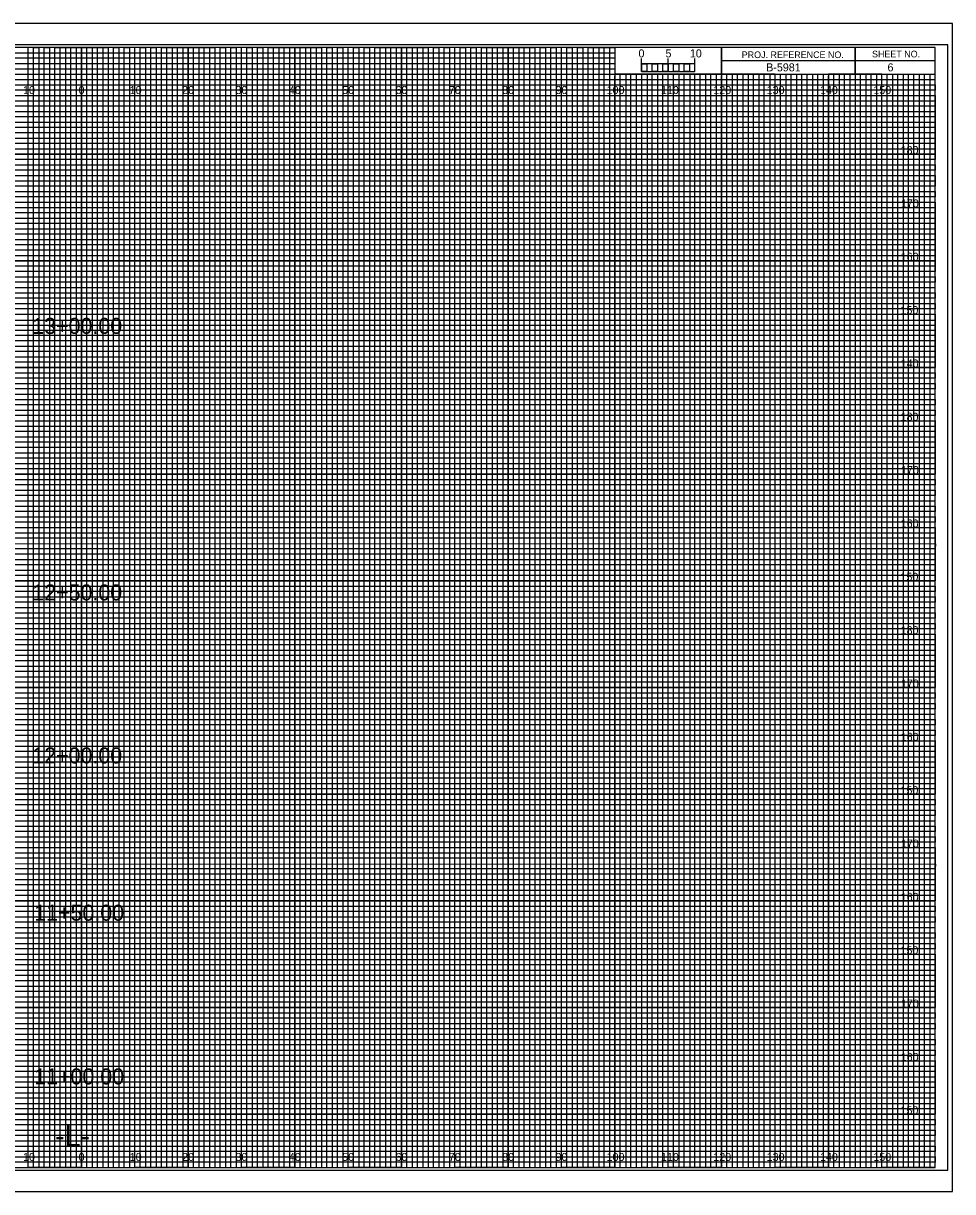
# Model space of a CAD drawing. Extents: x -13 to 323, y -5 to 4174.
# Drawn here: x 149.1 to 323.3, y -4.5 to 214.5 of the extents above; entities that cross this region are included whole.
import ezdxf

# ---------------------------------------------------------------- set-up
doc = ezdxf.new("R2010")
doc.units = 0
for name, color, linetype in [('Exist Cross Section Cell', 7, 'Continuous'), ('Exist XS Center Line Elevation Label', 7, 'Continuous'), ('Exist XS Ground Line', 7, 'Continuous'), ('Prop CMT Concrete Structures', 7, 'Continuous'), ('Prop CMT Guardrail Graphics', 7, 'Continuous'), ('Prop CMT Pvmt Course 1', 7, 'Continuous'), ('Prop CMT Pvmt Course 2', 7, 'Continuous'), ('Prop CMT Pvmt Course 3', 7, 'Continuous'), ('Prop CMT Pvmt Surface', 7, 'Continuous'), ('Prop CMT Shld Paved Course 1', 7, 'Continuous'), ('Prop CMT Shld Paved Course 2', 7, 'Continuous'), ('Prop CMT Shld Paved Course 3', 7, 'Continuous'), ('Prop CMT Subgrade Earthwork', 7, 'Continuous'), ('Prop XS Ditch Standard Text', 7, 'Continuous'), ('Prop XS SE Text', 7, 'Continuous'), ('Prop XS Side Slope Text', 7, 'Continuous'), ('Scratch_Level_0', 7, 'Continuous')]:
    doc.layers.add(name, color=color, linetype=linetype)

msp = doc.modelspace()

# ---------------------------------------------------------------- linework, layer by layer
at = {"layer": 'Exist XS Center Line Elevation Label'}
for points in [[(145, 0), (155, 0), (155, 210), (165, 210), (165, 0), (175, 0), (175, 210), (185, 210), (185, 0), (195, 0), (195, 210), (205, 210), (205, 0), (215, 0), (215, 210), (225, 210), (225, 0), (235, 0), (235, 210), (245, 210), (245, 0), (255, 0), (255, 210), (259.93, 210), (260, 210), (260, 205), (264.99, 205), (264.99, 0), (275, 0), (275, 205), (285, 205), (285, 0), (295, 0), (295, 205), (305, 205), (305, 0), (315, 0), (315, 205)], [(0, 205), (275, 205)], [(0, 185), (320, 185), (320, 195), (0, 195)], [(0, 165), (320, 165), (320, 175), (0, 175)], [(0, 145), (320, 145), (320, 155), (0, 155)], [(0, 125), (320, 125), (320, 135), (0, 135)], [(0, 105), (320, 105), (320, 115), (0, 115)], [(0, 85), (320, 85), (320, 95), (0, 95)], [(0, 65), (320, 65), (320, 75), (0, 75)], [(0, 45), (320, 45), (320, 55), (0, 55)], [(0, 25), (320, 25), (320, 35), (0, 35)], [(0, 5), (320, 5), (320, 15), (0, 15)]]:
    msp.add_lwpolyline(points, dxfattribs=at)
at = {"layer": 'Exist XS Ground Line'}
for p, q in [((150, 210), (140, 210)), ((150, 0), (150, 210)), ((170, 210), (160, 210)), ((160, 210), (160, 0)), ((170, 0), (170, 210)), ((190, 210), (180, 210)), ((180, 210), (180, 0)), ((190, 0), (190, 210)), ((210, 210), (200, 210)), ((200, 210), (200, 0)), ((210, 0), (210, 210)), ((230, 210), (220, 210)), ((220, 210), (220, 0)), ((230, 0), (230, 210)), ((250, 210), (240, 210)), ((240, 210), (240, 0)), ((250, 0), (250, 210)), ((260, 210), (260, 0)), ((270, 0), (270, 205)), ((290, 205), (280, 205)), ((280, 205), (280, 0)), ((290, 0), (290, 205)), ((310, 205), (300, 205)), ((300, 205), (300, 0)), ((310, 0), (310, 205)), ((160, 0), (150, 0)), ((180, 0), (170, 0)), ((200, 0), (190, 0)), ((220, 0), (210, 0)), ((240, 0), (230, 0)), ((260, 0), (250, 0)), ((280, 0), (270, 0)), ((300, 0), (290, 0)), ((320, 0), (310, 0)), ((320, 0), (320, 0))]:
    msp.add_line(p, q, dxfattribs=at)
for points in [[(0, 200), (320, 200), (320, 190), (0, 190)], [(0, 180), (320, 180), (320, 170), (0, 170)], [(0, 160), (320, 160), (320, 150), (0, 150)], [(0, 140), (320, 140), (320, 130), (0, 130)], [(0, 120), (320, 120), (320, 110), (0, 110)], [(0, 100), (320, 100), (320, 90), (0, 90)], [(0, 80), (320, 80), (320, 70), (0, 70)], [(0, 60), (320, 60), (320, 50), (0, 50)], [(0, 40), (320, 40), (320, 30), (0, 30)], [(0, 20), (320, 20), (320, 10), (0, 10)]]:
    msp.add_lwpolyline(points, dxfattribs=at)
at = {"layer": 'Prop CMT Pvmt Course 1'}
for p, q in [((323.3, 214.5), (-13.4, 214.5)), ((-13.4, -4.5), (323.3, -4.5))]:
    msp.add_line(p, q, dxfattribs=at)
at = {"layer": 'Prop CMT Pvmt Course 2'}
msp.add_lwpolyline([(-13.4, -4.5), (323.3, -4.5), (323.3, 214.5), (-13.4, 214.5)], close=True, dxfattribs=at)
at = {"layer": 'Prop CMT Pvmt Course 3'}
msp.add_lwpolyline([(-10.8, -0.5), (322.4, -0.5), (322.4, 210.5), (-10.8, 210.5)], close=True, dxfattribs=at)
at = {"layer": 'Prop CMT Shld Paved Course 1'}
for p, q in [((305, 210), (305, 205)), ((305, 205), (305, 210)), ((280, 207.5), (280, 205)), ((320, 207.49), (280, 207.49)), ((280, 205), (320, 205))]:
    msp.add_line(p, q, dxfattribs=at)
for points in [[(320, 210), (0, 210), (0, 0), (320, 0)], [(280, 210), (260, 210), (260, 205.03), (280, 205.03)], [(320, 210), (280, 210), (280, 205), (320, 205)]]:
    msp.add_lwpolyline(points, close=True, dxfattribs=at)
at = {"layer": 'Prop CMT Shld Paved Course 2'}
for p, q in [((267, 205), (266.01, 205)), ((266.01, 205), (266.01, 0)), ((267, 0), (267, 205)), ((269, 205), (268, 205)), ((268, 205), (268, 0)), ((269, 0), (269, 205)), ((266.01, 0), (265, 0)), ((268, 0), (267, 0))]:
    msp.add_line(p, q, dxfattribs=at)
for points in [[(150, 0), (151, 0), (151, 210), (152, 210), (152, 0)], [(152, 0), (153, 0), (153, 210), (154, 210), (154, 0)], [(155, 0), (156, 0), (156, 210), (157, 210), (157, 0)], [(157, 0), (158, 0), (158, 210), (159, 210), (159, 0)], [(160, 0), (161, 0), (161, 210), (162, 210), (162, 0)], [(162, 0), (163, 0), (163, 210), (164, 210), (164, 0)], [(165, 0), (166, 0), (166, 210), (167, 210), (167, 0)], [(167, 0), (168, 0), (168, 210), (169, 210), (169, 0)], [(170, 0), (171, 0), (171, 210), (172, 210), (172, 0)], [(172, 0), (173, 0), (173, 210), (174, 210), (174, 0)], [(175, 0), (176, 0), (176, 210), (177, 210), (177, 0)], [(177, 0), (178, 0), (178, 210), (179, 210), (179, 0)], [(180, 0), (181, 0), (181, 210), (182, 210), (182, 0)], [(182, 0), (183, 0), (183, 210), (184, 210), (184, 0)], [(185, 0), (186, 0), (186, 210), (187, 210), (187, 0)], [(187, 0), (188, 0), (188, 210), (189, 210), (189, 0)], [(190, 0), (191, 0), (191, 210), (192, 210), (192, 0)], [(192, 0), (193, 0), (193, 210), (194, 210), (194, 0)], [(195, 0), (196, 0), (196, 210), (197, 210), (197, 0)], [(197, 0), (198, 0), (198, 210), (199, 210), (199, 0)], [(200, 0), (201, 0), (201, 210), (202, 210), (202, 0)], [(202, 0), (203, 0), (203, 210), (204, 210), (204, 0)], [(205, 0), (206, 0), (206, 210), (207, 210), (207, 0)], [(207, 0), (208, 0), (208, 210), (209, 210), (209, 0)], [(210, 0), (211, 0), (211, 210), (212, 210), (212, 0)], [(212, 0), (213, 0), (213, 210), (214, 210), (214, 0)], [(215, 0), (216, 0), (216, 210), (217, 210), (217, 0)], [(217, 0), (218, 0), (218, 210), (219, 210), (219, 0)], [(220, 0), (221, 0), (221, 210), (222, 210), (222, 0)], [(222, 0), (223, 0), (223, 210), (224, 210), (224, 0)], [(225, 0), (226, 0), (226, 210), (227, 210), (227, 0)], [(227, 0), (228, 0), (228, 210), (229, 210), (229, 0)], [(230, 0), (231, 0), (231, 210), (232, 210), (232, 0)], [(232, 0), (233, 0), (233, 210), (234, 210), (234, 0)], [(235, 0), (236, 0), (236, 210), (237, 210), (237, 0)], [(237, 0), (238, 0), (238, 210), (239, 210), (239, 0)], [(240, 0), (241, 0), (241, 210), (242, 210), (242, 0)], [(242, 0), (243, 0), (243, 210), (244, 210), (244, 0)], [(245, 0), (246, 0), (246, 210), (247, 210), (247, 0)], [(247, 0), (248, 0), (248, 210), (249, 210), (249, 0)], [(250, 0), (251, 0), (251, 210), (252, 210), (252, 0)], [(252, 0), (253, 0), (253, 210), (254, 210), (254, 0)], [(255, 0), (256, 0), (256, 210), (257, 210), (257, 0)], [(257, 0), (258, 0), (258, 210), (259, 210), (259, 0)], [(260, 0), (261, 0), (261, 205), (262.02, 205), (262.02, 0)], [(262, 0), (263, 0), (263, 205), (263.99, 205), (263.99, 0)], [(270, 0), (270.98, 0), (270.98, 205), (272, 205), (272, 0)], [(272, 0), (273, 0), (273, 205), (274.05, 205), (274.05, 0)], [(275, 0), (276, 0), (276, 205), (277, 205), (277, 0)], [(277, 0), (278, 0), (278, 205), (279, 205), (279, 0)], [(280, 0), (281, 0), (281, 205), (282, 205), (282, 0)], [(282, 0), (283, 0), (283, 205), (284, 205), (284, 0)], [(285, 0), (286, 0), (286, 205), (287, 205), (287, 0)], [(287, 0), (288, 0), (288, 205), (289, 205), (289, 0)], [(290, 0), (291, 0), (291, 205), (292, 205), (292, 0)], [(292, 0), (293, 0), (293, 205), (294, 205), (294, 0)], [(295, 0), (296, 0), (296, 205), (297, 205), (297, 0)], [(297, 0), (298, 0), (298, 205), (299, 205), (299, 0)], [(300, 0), (301, 0), (301, 205), (302, 205), (302, 0)], [(302, 0), (303, 0), (303, 205), (304, 205), (304, 0)], [(305, 0), (306, 0), (306, 205), (307, 205), (307, 0)], [(307, 0), (308, 0), (308, 205), (309, 205), (309, 0)], [(310, 0), (311, 0), (311, 205), (312, 205), (312, 0)], [(312, 0), (313, 0), (313, 205), (314, 205), (314, 0)], [(315, 0), (316, 0), (316, 205), (317, 205), (317, 0)], [(317, 0), (318, 0), (318, 205), (319, 205), (319, 0)]]:
    msp.add_lwpolyline(points, dxfattribs=at)
at = {"layer": 'Prop CMT Shld Paved Course 3'}
for p, q in [((265, 205.49), (265, 207.9)), ((265, 206.9), (265, 207.9)), ((270, 205.49), (270, 207.9)), ((275, 205.49), (275, 207.9)), ((275, 206.9), (275, 207.9))]:
    msp.add_line(p, q, dxfattribs=at)
for points in [[(275, 206.9), (265, 206.9), (265, 205.49), (275, 205.49)], [(265, 206.9), (266, 206.9), (266, 205.49), (265, 205.49)], [(267, 206.9), (268, 206.9), (268, 205.49), (267, 205.49)], [(269, 206.9), (270, 206.9), (270, 205.49), (269, 205.49)], [(271, 206.9), (272, 206.9), (272, 205.49), (271, 205.49)], [(273, 206.9), (274, 206.9), (274, 205.49), (273, 205.49)]]:
    msp.add_lwpolyline(points, close=True, dxfattribs=at)
at = {"layer": 'Prop CMT Subgrade Earthwork'}
for p, q in [((150, 0), (150, 210)), ((160, 0), (160, 210)), ((170, 0), (170, 210)), ((180, 0), (180, 210)), ((190, 0), (190, 210)), ((200, 0), (200, 210)), ((210, 0), (210, 210)), ((220, 0), (220, 210)), ((230, 0), (230, 210)), ((240, 0), (240, 210)), ((250, 0), (250, 210)), ((260, 0), (260, 204.69)), ((270, 0), (270, 204.69)), ((280, 0), (280, 204.69)), ((290, 0), (290, 204.69)), ((300, 0), (300, 204.69)), ((310, 0), (310, 204.69)), ((0, 200), (320, 200)), ((0, 190), (320, 190)), ((0, 180), (320, 180)), ((0, 170), (320, 170)), ((0, 160), (320, 160)), ((0, 150), (320, 150)), ((0, 140), (320, 140)), ((0, 130), (320, 130)), ((0, 120), (320, 120)), ((0, 110), (320, 110)), ((0, 100), (320, 100)), ((0, 90), (320, 90)), ((0, 80), (320, 80)), ((0, 70), (320, 70)), ((0, 60), (320, 60)), ((0, 50), (320, 50)), ((0, 40), (320, 40)), ((0, 30), (320, 30)), ((0, 20), (320, 20)), ((0, 10), (320, 10))]:
    msp.add_line(p, q, dxfattribs=at)
at = {"layer": 'Scratch_Level_0'}
for p, q in [((0, 209), (260, 209)), ((260, 209), (260, 207.98)), ((260, 207.98), (0, 207.98)), ((0, 207), (260, 207)), ((260, 205.89), (0, 205.89)), ((260, 207), (260, 205.89)), ((0, 204), (320, 204))]:
    msp.add_line(p, q, dxfattribs=at)
for points in [[(0, 203), (270, 203), (320, 203), (320, 202), (0, 202)], [(0, 201), (320, 201), (320, 199), (0, 199)], [(0, 198), (320, 198), (320, 197), (0, 196.98)], [(0, 196), (320, 196), (320, 194), (0, 194)], [(0, 193), (320, 193), (320, 192), (0, 192)], [(0, 191), (320, 191), (320, 189), (0, 189)], [(0, 188), (320, 188), (320, 187), (0, 187)], [(0, 186), (320, 186), (320, 184), (0, 184)], [(0, 183), (320, 183), (320, 182), (0, 182)], [(0, 181), (320, 181), (320, 179), (0, 179)], [(0, 178), (320, 178), (320, 177), (0, 177)], [(0, 176), (320, 176), (320, 173.95), (320, 173), (320, 172), (0, 172)], [(0, 174), (320, 174), (320, 173), (0, 173)], [(0, 171), (320, 171), (320, 169), (0, 169.03)], [(0, 169.03), (320, 169), (320, 168), (0, 168)], [(0, 167), (320, 167), (320, 166), (0, 166)], [(0, 164), (320, 164), (320, 163), (0, 163)], [(0, 162), (320, 162), (320, 161), (0, 161)], [(-0.07, 158.89), (320, 158.89), (320, 157.88), (-0.07, 157.88)], [(0, 157), (320, 157), (320, 156), (0, 156)], [(0, 154), (320, 154), (320, 153), (0, 153)], [(0, 152), (320, 152), (320, 151), (0, 151)], [(0, 149), (320, 149), (320, 148), (0, 148)], [(0, 147), (320, 147), (320, 146), (0, 146)], [(0, 144), (320, 144), (320, 143), (0, 143)], [(0, 142), (320, 142), (320, 141), (0, 141)], [(0, 139), (320, 139), (319.99, 137.98), (0, 138)], [(0, 137), (320, 137), (320, 136), (0, 136)], [(0, 134), (320, 134), (320, 133), (0, 133)], [(0, 132), (320, 132), (320, 131), (0, 131)], [(0, 129), (320, 129), (320, 128), (0, 128)], [(0, 127), (320, 127), (320, 126), (0, 126)], [(0, 124), (320, 124), (320, 123), (0, 123)], [(0, 122), (320, 122), (320, 121), (0, 121)], [(0, 119), (320, 119), (320, 118), (0, 118)], [(0, 116.99), (320.07, 116.91), (320, 116), (0, 116)], [(0, 114), (320, 114), (320, 113), (0, 113)], [(0, 112), (320, 112), (320, 111), (0, 111)], [(0, 109), (320, 109), (320, 108), (0, 108)], [(0, 107), (320, 107), (320, 106), (0, 106)], [(0, 104), (320, 104), (320, 103), (0, 103)], [(0, 102), (320, 102), (320, 101), (0, 101)], [(0, 99), (320, 99), (320, 98), (0, 98)], [(0, 97), (320, 97), (320, 96), (0, 96)], [(0, 94), (320, 94), (320, 93), (0, 93)], [(0, 92), (320, 92), (320, 91), (0, 91)], [(0, 89), (320, 89), (320, 88), (0, 88)], [(0, 87), (320, 87), (320, 86), (0, 86)], [(0, 84), (320, 84), (320, 83), (0, 83)], [(0, 82), (320, 82), (320, 81), (0, 81)], [(0, 79), (320, 79), (319.99, 77.98), (0, 78)], [(0, 77), (320, 77), (320, 76), (0, 76)], [(0, 74), (320, 74), (320, 73), (0, 73)], [(0, 72), (320, 72), (320, 71), (0, 71)], [(0, 69), (320, 69), (320, 68), (0, 68)], [(0, 67), (320, 67), (320, 66), (0, 66)], [(0, 64), (320, 64), (320, 63), (0, 63)], [(0, 62), (320, 62), (320, 61), (0, 61)], [(0, 59), (320, 59), (320, 58), (0, 58)], [(0, 56.99), (320.07, 56.91), (320, 56), (0, 56)], [(0, 54), (320, 54), (320, 53), (0, 53)], [(0, 52), (320, 52), (320, 51), (0, 51)], [(0, 49), (320, 49), (320, 48), (0, 48)], [(0, 47), (320, 47), (320, 46), (0, 46)], [(0, 44), (320, 44), (320, 43), (0, 43)], [(0, 42), (320, 42), (320, 41), (0, 41)], [(0, 39), (320, 39), (320, 38), (0, 38)], [(0, 37), (320, 37), (320, 36), (0, 36)], [(0, 34), (320, 34), (320, 33), (0, 33)], [(0, 32), (320, 32), (320, 31), (0, 31)], [(0, 29), (320, 29), (320, 28), (0, 28)], [(0, 27), (320, 27), (320, 26), (0, 26)], [(0, 24), (320, 24), (320, 23), (0, 23)], [(0, 22), (320, 22), (320, 21), (0, 21)], [(0, 19), (320, 19), (320, 18), (0, 18)], [(0, 17), (320, 17), (320, 16), (0, 16)], [(0, 14), (320, 14), (320, 13), (0, 13)], [(0, 12), (320, 12), (320, 11), (0, 11)], [(0, 9), (320, 9), (320, 8), (0, 8)], [(0, 7), (320, 7), (320, 6), (0, 6)], [(0, 4), (320, 4), (320, 3), (0, 3)], [(0, 2), (320, 2), (320, 1), (0, 1)]]:
    msp.add_lwpolyline(points, dxfattribs=at)

# ---------------------------------------------------------------- texts
at = {"layer": 'Exist Cross Section Cell'}
for s, p in [('10', (149.04, 201.25)), ('0', (159.45, 201.25)), ('0', (159.45, 201.25)), ('10', (169.04, 201.25)), ('20', (178.86, 201.25)), ('30', (188.86, 201.25)), ('40', (198.86, 201.25)), ('50', (208.86, 201.25)), ('60', (218.86, 201.25)), ('70', (228.86, 201.25)), ('80', (238.86, 201.25)), ('90', (248.86, 201.25)), ('100', (258.44, 201.25)), ('110', (268.62, 201.25)), ('120', (278.44, 201.25)), ('130', (288.44, 201.25)), ('140', (298.44, 201.25)), ('150', (308.44, 201.25)), ('10', (149.04, 1.25)), ('0', (159.45, 1.25)), ('0', (159.45, 1.25)), ('10', (169.04, 1.25)), ('20', (178.86, 1.25)), ('30', (188.86, 1.25)), ('40', (198.86, 1.25)), ('50', (208.86, 1.25)), ('60', (218.86, 1.25)), ('70', (228.86, 1.25)), ('80', (238.86, 1.25)), ('90', (248.86, 1.25)), ('100', (258.44, 1.25)), ('110', (268.62, 1.25)), ('120', (278.44, 1.25)), ('130', (288.44, 1.25)), ('140', (298.44, 1.25)), ('150', (308.44, 1.25))]:
    msp.add_text(s, height=1.5, dxfattribs=at).set_placement(p)
at = {"layer": 'Prop CMT Concrete Structures'}
for s, p in [('13+00.00', (150.77, 156.29)), ('12+50.00', (150.77, 106.33)), ('12+00.00', (150.77, 75.77)), ('11+50.00', (151.13, 46.29)), ('11+00.00', (151.13, 15.6))]:
    msp.add_text(s, height=3, dxfattribs=at).set_placement(p)
at = {"layer": 'Prop CMT Guardrail Graphics'}
for s, p in [('180', (313.55, 190)), ('170', (313.61, 180)), ('160', (313.57, 170)), ('150', (313.52, 160)), ('140', (313.57, 150)), ('180', (313.55, 140)), ('170', (313.61, 130)), ('160', (313.57, 120)), ('150', (313.52, 110)), ('180', (313.55, 100)), ('170', (313.61, 90)), ('160', (313.57, 80)), ('150', (313.52, 70)), ('170', (313.61, 60)), ('160', (313.57, 50)), ('150', (313.52, 40)), ('170', (313.61, 30)), ('160', (313.57, 20)), ('150', (313.52, 10))]:
    msp.add_text(s, height=1.5, dxfattribs=at).set_placement(p)
at = {"layer": 'Prop CMT Pvmt Surface'}
for s, p in [('5', (269.47, 208.12)), ('10', (274.04, 208.12))]:
    msp.add_text(s, height=1.5, dxfattribs=at).set_placement(p)
at = {"layer": 'Prop CMT Shld Paved Course 1'}
for s, p in [('PROJ. REFERENCE NO.', (283.77, 207.99)), ('SHEET NO.', (308.19, 208.12))]:
    msp.add_text(s, height=1.25, dxfattribs=at).set_placement(p)
at = {"layer": 'Prop CMT Shld Paved Course 3'}
msp.add_text('0', height=1.5, dxfattribs=at).set_placement((264.41, 208.12))
at = {"layer": 'Prop XS Ditch Standard Text'}
msp.add_text('-L-', height=4, dxfattribs=at).set_placement((155.06, 4))
at = {"layer": 'Prop XS SE Text'}
msp.add_text(' B-5981', height=1.5, dxfattribs=at).set_placement((287.79, 205.5))
at = {"layer": 'Prop XS Side Slope Text'}
msp.add_text('6', height=1.5, dxfattribs=at).set_placement((311.09, 205.5))

doc.saveas('drawing.dxf')
